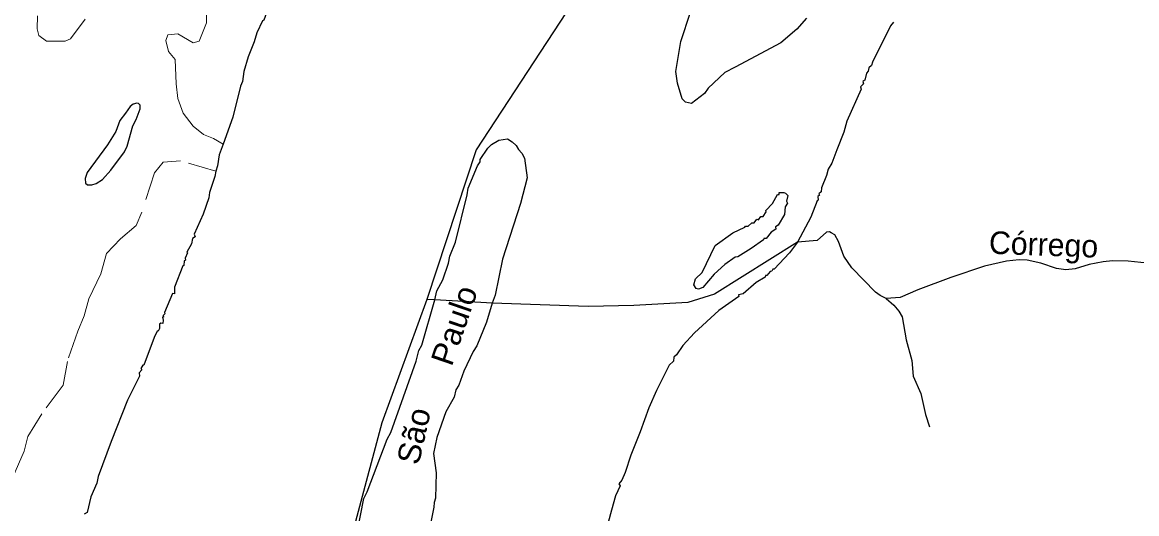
# Model space of a CAD drawing. Extents: x 344.9 to 371, y 7566.4 to 7594.3.
# Drawn here: x 362.817 to 366.76, y 7569.185 to 7570.925 of the extents above; entities that cross this region are included whole.
import ezdxf
from ezdxf.enums import TextEntityAlignment as Align

# ---------------------------------------------------------------- set-up
doc = ezdxf.new("R2010")
doc.units = 0
doc.header["$LTSCALE"] = 0.04
doc.linetypes.add('SHORT_DASHED', pattern=[2.7, 1.5, -1.2])
for name, color, linetype, lineweight in [('17', 7, 'SHORT_DASHED', 13), ('2', 7, 'Continuous', 25), ('55', 7, 'Continuous', 25), ('7', 7, 'Continuous', 25)]:
    doc.layers.add(name, color=color, linetype=linetype, lineweight=lineweight)
doc.layers.add('61', color=7, linetype='Continuous')

msp = doc.modelspace()

# ---------------------------------------------------------------- linework, layer by layer
at = {"layer": '17'}
for points in [[(363.0392, 7570.936), (362.9875, 7570.8659), (362.9691, 7570.8576), (362.9026, 7570.8576), (362.875, 7570.8779), (362.8694, 7570.9019), (362.8713, 7570.948)], [(363.4689, 7570.974), (363.4689, 7570.9224), (363.4431, 7570.8578), (363.421, 7570.8523), (363.3675, 7570.8836), (363.3324, 7570.8799), (363.325, 7570.8596), (363.3342, 7570.8209), (363.3582, 7570.7932), (363.3619, 7570.7065), (363.3675, 7570.6548), (363.3859, 7570.6032), (363.421, 7570.5571), (363.4579, 7570.5275), (363.4929, 7570.5128), (363.5274, 7570.4931)], [(363.5011, 7570.3979), (363.3768, 7570.4345), (363.3159, 7570.429), (363.2845, 7570.3921), (363.2402, 7570.2519), (363.2199, 7570.2057), (363.1646, 7570.1578), (363.1148, 7570.1061), (363.0945, 7570.0342), (363.052, 7569.9456), (363.0354, 7569.8847), (363.0133, 7569.8312), (362.9764, 7569.7233), (362.9616, 7569.6402), (362.886, 7569.5388), (362.8362, 7569.4576), (362.8233, 7569.4059), (362.7477, 7569.2343), (362.7292, 7569.1679)]]:
    msp.add_lwpolyline(points, dxfattribs=at)
at = {"layer": '2'}
for points in [[(365.339, 7570.7661), (365.3021, 7570.7472), (365.2433, 7570.6908), (365.2306, 7570.6726), (365.1846, 7570.6376), (365.1639, 7570.6416), (365.152, 7570.6535), (365.1353, 7570.7091), (365.129, 7570.7504), (365.1464, 7570.8568), (365.1814, 7570.9601), (365.1893, 7571.0014), (365.1861, 7571.0633), (365.1885, 7571.1046), (365.2171, 7571.1872), (365.2703, 7571.2983), (365.2933, 7571.3762), (365.3037, 7571.4381), (365.3061, 7571.4873), (365.3029, 7571.5715)], [(363.8211, 7571.3635), (363.7743, 7571.2301), (363.7457, 7571.1252), (363.7147, 7571.0315), (363.6917, 7570.9743), (363.6806, 7570.9585), (363.671, 7570.9322), (363.6663, 7570.9299), (363.6472, 7570.887), (363.6377, 7570.8552), (363.6162, 7570.8028), (363.6004, 7570.7504), (363.5956, 7570.7155), (363.5884, 7570.698), (363.5614, 7570.5884), (363.5274, 7570.4931)], [(365.5911, 7570.9394), (365.557, 7570.9005), (365.5006, 7570.852), (365.339, 7570.7661)], [(365.8992, 7570.9251), (365.8881, 7570.9124), (365.8246, 7570.7838)], [(365.8246, 7570.7838), (365.8214, 7570.7718), (365.8119, 7570.7639), (365.8095, 7570.7512), (365.8039, 7570.7449), (365.7976, 7570.7194), (365.7912, 7570.7147), (365.7928, 7570.7067), (365.7825, 7570.6964), (365.7849, 7570.6877), (365.7341, 7570.5741), (365.723, 7570.5352), (365.6991, 7570.4725), (365.6809, 7570.4264), (365.6682, 7570.4042), (365.6626, 7570.382), (365.6451, 7570.339), (365.6435, 7570.324), (365.6348, 7570.3176), (365.638, 7570.3121), (365.6316, 7570.3081), (365.6332, 7570.2946), (365.6292, 7570.2922), (365.6067, 7570.2351), (365.5601, 7570.1458)], [(364.276, 7569.9417), (364.2841, 7569.9738), (364.3047, 7570.0127), (364.3253, 7570.0723), (364.3301, 7570.0961), (364.3492, 7570.1461), (364.3913, 7570.3137), (364.3944, 7570.3375), (364.427, 7570.4169), (364.4365, 7570.4304), (364.4365, 7570.4391), (364.4635, 7570.4788), (364.477, 7570.4915), (364.5032, 7570.5074), (364.5334, 7570.5114), (364.5501, 7570.5018), (364.5644, 7570.4884), (364.5731, 7570.474)], [(363.5274, 7570.4931), (363.5138, 7570.455), (363.5074, 7570.4169), (363.5011, 7570.3979)], [(364.5731, 7570.474), (364.5842, 7570.4614), (364.5938, 7570.4439), (364.6033, 7570.374), (364.5795, 7570.2827), (364.5159, 7570.0858), (364.4897, 7569.9579), (364.4799, 7569.93)], [(363.5011, 7570.3979), (363.4979, 7570.3788), (363.4789, 7570.3216), (363.4765, 7570.3026), (363.4566, 7570.2454), (363.4249, 7570.1739), (363.428, 7570.1652), (363.4193, 7570.1596), (363.4153, 7570.1406), (363.3995, 7570.1103), (363.401, 7570.108), (363.3931, 7570.0897), (363.3947, 7570.0826), (363.3892, 7570.0802), (363.3883, 7570.0635), (363.3852, 7570.0627), (363.355, 7569.9865), (363.355, 7569.9635), (363.3478, 7569.9643), (363.3201, 7569.8975), (363.3208, 7569.892), (363.3153, 7569.8864), (363.3169, 7569.8809), (363.3129, 7569.8801)], [(365.5601, 7570.1458), (365.5319, 7570.1087), (365.4776, 7570.0508), (365.4728, 7570.05), (365.4688, 7570.0429), (365.4633, 7570.0421), (365.4514, 7570.0286), (365.4466, 7570.0278), (365.445, 7570.0222), (365.4133, 7570.0032), (365.3672, 7569.9635), (365.3505, 7569.9595), (365.3516, 7569.954), (365.2819, 7569.9043), (365.1957, 7569.8245), (365.1544, 7569.7808), (365.1314, 7569.7475), (365.1226, 7569.7395), (365.121, 7569.7253), (365.1052, 7569.7102), (365.0607, 7569.6212), (365.0337, 7569.5593), (365.0035, 7569.4751)], [(363.9524, 7568.883), (363.9736, 7568.9812), (363.9934, 7569.0527), (364.003, 7569.1241), (364.0252, 7569.2385), (364.0371, 7569.2623), (364.1078, 7569.4481), (364.1205, 7569.4719), (364.2102, 7569.7245), (364.2197, 7569.7626), (364.2301, 7569.7816), (364.276, 7569.9417)], [(364.4799, 7569.93), (364.4596, 7569.8626), (364.4254, 7569.7785), (364.4127, 7569.7594), (364.3793, 7569.6895), (364.3611, 7569.6395), (364.3508, 7569.6228), (364.3444, 7569.5974), (364.3159, 7569.5458), (364.2833, 7569.4545), (364.2722, 7569.3973), (364.2817, 7569.329), (364.2793, 7569.2401), (364.2737, 7569.2242), (364.2729, 7569.2083), (364.2324, 7569.0098)], [(363.3129, 7569.8801), (363.3153, 7569.8698), (363.3137, 7569.8586), (363.3065, 7569.8594), (363.3026, 7569.8554), (363.3018, 7569.8404), (363.2978, 7569.8308), (363.2938, 7569.8309), (363.2835, 7569.8086), (363.247, 7569.711), (363.243, 7569.7102), (363.2367, 7569.699), (363.2399, 7569.6935), (363.2303, 7569.6839), (363.2311, 7569.6712), (363.189, 7569.5863), (363.131, 7569.4402), (363.085, 7569.3163), (363.081, 7569.2925), (363.0596, 7569.2448), (363.0469, 7569.1893), (363.0358, 7569.1829)], [(365.0035, 7569.4751), (364.9702, 7569.3925), (364.9495, 7569.3306), (364.9376, 7569.3036), (364.9273, 7569.2901), (364.932, 7569.2837), (364.9162, 7569.248), (364.9011, 7569.1972), (364.8812, 7569.1225)]]:
    msp.add_lwpolyline(points, dxfattribs=at)
for points in [[(363.1819, 7570.6027), (363.1621, 7570.5768), (363.1479, 7570.5383), (363.1188, 7570.491), (363.0464, 7570.3922), (363.0394, 7570.3719), (363.0408, 7570.3549), (363.0473, 7570.3493), (363.0634, 7570.3493), (363.0782, 7570.3537), (363.1003, 7570.3685), (363.1303, 7570.4015), (363.1783, 7570.4663), (363.1875, 7570.4857), (363.2082, 7570.5586), (363.2202, 7570.5808), (363.2336, 7570.6182), (363.2345, 7570.6315), (363.2285, 7570.6371), (363.2216, 7570.6385), (363.2091, 7570.6343), (363.198, 7570.6265)], [(365.339, 7570.0928), (365.3025, 7570.0672), (365.2647, 7570.0333), (365.225, 7569.986), (365.2089, 7569.9796), (365.201, 7569.9823), (365.1927, 7569.9952), (365.1991, 7570.0164), (365.2221, 7570.0388), (365.2678, 7570.1348), (365.3307, 7570.1794), (365.3736, 7570.1993), (365.3752, 7570.2033), (365.3847, 7570.2033), (365.3982, 7570.2144), (365.4069, 7570.2144), (365.4156, 7570.2279), (365.422, 7570.2255), (365.4299, 7570.2366), (365.4379, 7570.2366), (365.449, 7570.2533), (365.4474, 7570.258), (365.4712, 7570.2835), (365.4887, 7570.3152), (365.4943, 7570.3152), (365.4951, 7570.3216), (365.5117, 7570.3224), (365.5173, 7570.3192), (365.526, 7570.3113), (365.5212, 7570.2914), (365.5244, 7570.2843), (365.5165, 7570.2708), (365.5133, 7570.2446), (365.4911, 7570.2064), (365.4823, 7570.2009), (365.4832, 7570.1922), (365.4665, 7570.1818), (365.4482, 7570.1588), (365.441, 7570.1596), (365.4395, 7570.154), (365.3958, 7570.1239), (365.349, 7570.0945)]]:
    msp.add_lwpolyline(points, close=True, dxfattribs=at)
at = {"layer": '55'}
for points in [[(365.4153, 7572.3691), (364.9672, 7571.533), (364.7635, 7570.9941), (364.4224, 7570.4736), (364.2487, 7569.9432)], [(365.5601, 7570.1458), (365.2657, 7569.9617), (365.172, 7569.9328), (364.981, 7569.922), (364.8188, 7569.9184), (364.4799, 7569.93), (364.276, 7569.9417), (364.2487, 7569.9432)], [(364.2487, 7569.9432), (364.0895, 7569.5068), (363.9121, 7568.8431), (363.8211, 7568.0189), (363.6699, 7567.4867), (363.5122, 7567.0727), (363.4067, 7566.5507)]]:
    msp.add_lwpolyline(points, dxfattribs=at)
at = {"layer": '7'}
for points in [[(365.8739, 7569.9461), (365.8522, 7569.9567), (365.8352, 7569.9696), (365.7515, 7570.0548), (365.7237, 7570.0961), (365.7047, 7570.1485), (365.6912, 7570.1715), (365.6793, 7570.1794), (365.673, 7570.1826), (365.6618, 7570.1818), (365.6293, 7570.1516), (365.5601, 7570.1458)], [(366.6409, 7570.077), (366.5917, 7570.0667), (366.5425, 7570.0516), (366.5091, 7570.0484), (366.4758, 7570.0532), (366.4202, 7570.0722), (366.3725, 7570.0818), (366.344, 7570.0834), (366.2995, 7570.0786), (366.2217, 7570.0611), (366.1026, 7570.0206), (365.985, 7569.9777), (365.9223, 7569.95), (365.8739, 7569.9461)], [(367.6891, 7569.9079), (367.6097, 7569.9245), (367.5208, 7569.9595), (367.4509, 7569.9801), (367.3683, 7570.0103), (367.2905, 7570.0294), (367.2508, 7570.0349), (367.1253, 7570.0365), (367.0809, 7570.0429), (367.0126, 7570.0627), (366.9729, 7570.0699), (366.8411, 7570.0675), (366.7299, 7570.0786), (366.6743, 7570.0802), (366.6409, 7570.077)], [(365.8739, 7569.9461), (365.9008, 7569.923), (365.9183, 7569.9015), (365.9294, 7569.8817), (365.9445, 7569.8007), (365.9644, 7569.7276), (365.9683, 7569.6721), (365.9961, 7569.6101), (366.0128, 7569.5363), (366.0271, 7569.4918)]]:
    msp.add_lwpolyline(points, dxfattribs=at)

# ---------------------------------------------------------------- texts
at = {"layer": '61'}
msp.add_text('Córrego', height=0.08, rotation=357.881, dxfattribs=at).set_placement((366.429, 7570.0983), align=Align.CENTER)
at = {"layer": '61', "width": 1.05}
for s, rotation, p in [('Paulo', 71.005, (364.3829, 7569.8387)), ('São', 77.308, (364.2412, 7569.4514))]:
    msp.add_text(s, height=0.08, rotation=rotation, dxfattribs=at).set_placement(p, align=Align.CENTER)

doc.saveas('drawing.dxf')
